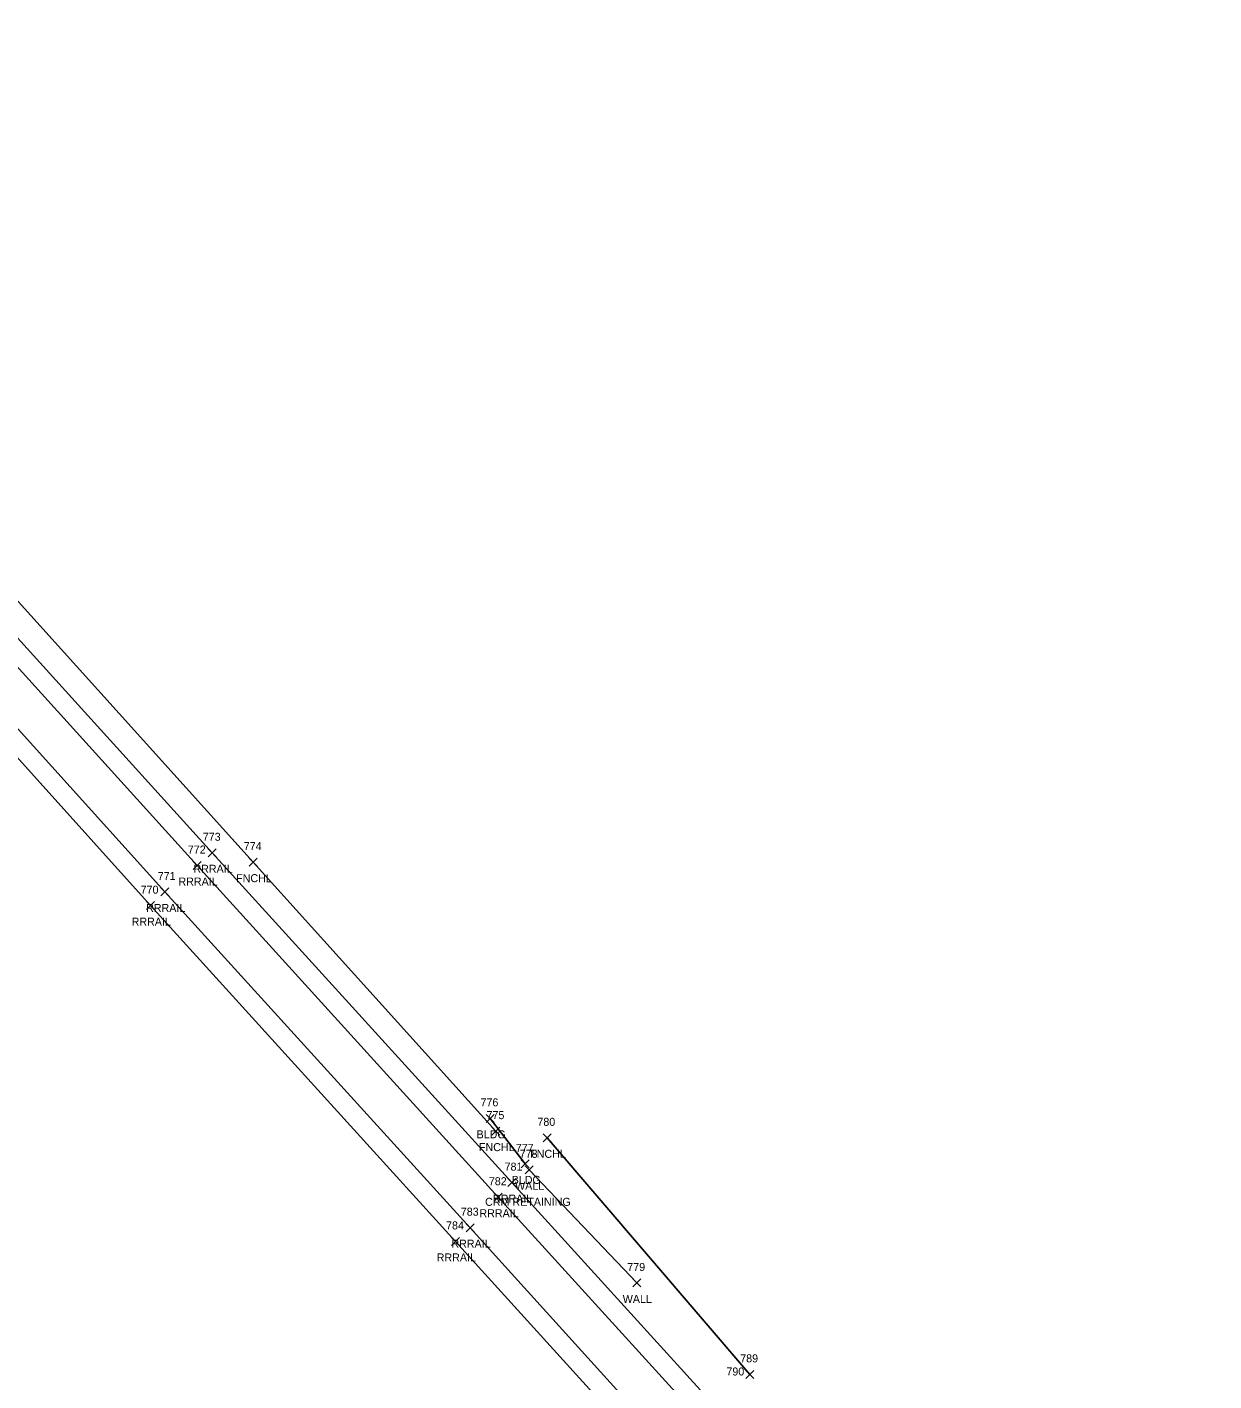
# Model space of a CAD drawing. Extents: x 1638029 to 1638889, y 618768 to 620505.
# Drawn here: x 1638352.1 to 1638648.8, y 619965.1 to 620303.6 of the extents above; entities that cross this region are included whole.
import ezdxf

# ---------------------------------------------------------------- set-up
doc = ezdxf.new("R2010")
doc.units = 0
for name, color, linetype in [('L_A', 7, 'Continuous'), ('L_C', 7, 'Continuous'), ('L_I', 7, 'Continuous'), ('L_TIC', 7, 'Continuous'), ('LBC', 7, 'Continuous'), ('LFNC', 7, 'Continuous'), ('LW', 7, 'Continuous'), ('R_A', 7, 'Continuous'), ('R_I', 7, 'Continuous'), ('R_TIC', 7, 'Continuous'), ('RR', 7, 'Continuous')]:
    doc.layers.add(name, color=color, linetype=linetype)

msp = doc.modelspace()

# ---------------------------------------------------------------- linework, layer by layer
at = {"layer": 'L_TIC'}
for points in [[(1638407.62, 620093.82), (1638409.62, 620095.82)], [(1638409.62, 620093.82), (1638407.62, 620095.82)], [(1638466.87, 620029.78), (1638468.87, 620031.78)], [(1638468.87, 620029.78), (1638466.87, 620031.78)], [(1638468.31, 620026.58), (1638470.31, 620028.58)], [(1638470.31, 620026.58), (1638468.31, 620028.58)], [(1638481.12, 620024.91), (1638483.12, 620026.91)], [(1638483.12, 620024.91), (1638481.12, 620026.91)], [(1638475.65, 620018.4), (1638477.65, 620020.4)], [(1638477.65, 620018.4), (1638475.65, 620020.4)], [(1638476.6, 620016.91), (1638478.6, 620018.91)], [(1638478.6, 620016.91), (1638476.6, 620018.91)], [(1638503.51, 619988.62), (1638505.51, 619990.62)], [(1638505.51, 619988.62), (1638503.51, 619990.62)], [(1638531.74, 619965.78), (1638533.74, 619967.78)], [(1638533.74, 619965.78), (1638531.74, 619967.78)]]:
    msp.add_lwpolyline(points, dxfattribs=at)
at = {"layer": 'LBC'}
msp.add_lwpolyline([(1638467.87, 620030.78), (1638476.65, 620019.4)], dxfattribs=at)
at = {"layer": 'LFNC'}
for points in [[(1638283.51, 620233.52), (1638308.83, 620205.48), (1638408.62, 620094.82), (1638469.31, 620027.58)], [(1638482.12, 620025.91), (1638532.74, 619966.78)]]:
    msp.add_lwpolyline(points, dxfattribs=at)
at = {"layer": 'LW'}
msp.add_lwpolyline([(1638477.6, 620017.91), (1638504.51, 619989.62)], dxfattribs=at)
at = {"layer": 'R_TIC'}
for points in [[(1638397.39, 620096.17), (1638399.39, 620098.17)], [(1638399.39, 620096.17), (1638397.39, 620098.17)], [(1638393.65, 620092.98), (1638395.65, 620094.98)], [(1638395.65, 620092.98), (1638393.65, 620094.98)], [(1638385.57, 620086.37), (1638387.57, 620088.37)], [(1638387.57, 620086.37), (1638385.57, 620088.37)], [(1638381.95, 620082.95), (1638383.95, 620084.95)], [(1638383.95, 620082.95), (1638381.95, 620084.95)], [(1638472.27, 620013.71), (1638474.27, 620015.71)], [(1638474.27, 620013.71), (1638472.27, 620015.71)], [(1638468.89, 620010.06), (1638470.89, 620012.06)], [(1638470.89, 620010.06), (1638468.89, 620012.06)], [(1638461.88, 620002.45), (1638463.88, 620004.45)], [(1638463.88, 620002.45), (1638461.88, 620004.45)], [(1638458.2, 619999.01), (1638460.2, 620001.01)], [(1638460.2, 619999.01), (1638458.2, 620001.01)]]:
    msp.add_lwpolyline(points, dxfattribs=at)
at = {"layer": 'RR'}
for points in [[(1638117.2, 620500.03), (1638126.53, 620471.54), (1638137.23, 620443.64), (1638146.58, 620422.4), (1638162.72, 620390.25), (1638178.78, 620362.34), (1638206.73, 620318.99), (1638221.73, 620298.51), (1638231.34, 620286.06), (1638247.72, 620265.63), (1638271.6, 620237.56), (1638302.87, 620202.63), (1638319.77, 620183.84), (1638340.9, 620160.55), (1638398.39, 620097.17), (1638473.27, 620014.71), (1638530.28, 619952.03), (1638576.7, 619900.87), (1638602.43, 619872.23), (1638628.75, 619841.68), (1638648.78, 619815.3)], [(1638112.47, 620498.54), (1638121.85, 620470.07), (1638132.7, 620441.63), (1638142.09, 620420.29), (1638158.38, 620387.98), (1638174.67, 620359.55), (1638202.82, 620316.02), (1638218.22, 620294.92), (1638227.34, 620283.09), (1638243.87, 620262.45), (1638266.59, 620235.71), (1638298.84, 620199.7), (1638316.08, 620180.56), (1638337.37, 620157.11), (1638394.65, 620093.98), (1638469.89, 620011.06), (1638526.76, 619948.51), (1638573.25, 619897.28), (1638598.73, 619868.77), (1638625.03, 619838.36), (1638644.96, 619812.19)], [(1638221.31, 620298.23), (1638230.93, 620285.59), (1638246.32, 620264.59), (1638266.59, 620235.71), (1638293.43, 620196.21), (1638308.67, 620175.28), (1638330, 620150.06), (1638386.57, 620087.37), (1638462.88, 620003.45), (1638518.49, 619941.93), (1638565.29, 619889.65), (1638590.21, 619860.51), (1638615.55, 619828.52), (1638634.05, 619803.38)], [(1638218.22, 620294.92), (1638227.01, 620282.65), (1638242.37, 620261.41), (1638263.25, 620232.01), (1638289.27, 620193.61), (1638304.74, 620172.29), (1638326.19, 620147.02), (1638382.95, 620083.95), (1638459.2, 620000.01), (1638514.66, 619938.83), (1638562.01, 619885.9), (1638586.02, 619857.93), (1638612.02, 619825.03), (1638629.76, 619800.91)]]:
    msp.add_lwpolyline(points, dxfattribs=at)

# ---------------------------------------------------------------- texts
at = {"layer": 'L_A'}
for s, p in [('FNCHL', (1638404.37, 620089.82)), ('BLDG', (1638464.46, 620025.78)), ('FNCHL', (1638465.06, 620022.58)), ('FNCHL', (1638477.87, 620020.91)), ('BLDG', (1638473.24, 620014.4)), ('WALL', (1638474.09, 620012.91)), ('WALL', (1638501, 619984.62))]:
    msp.add_text(s, height=2, dxfattribs=at).set_placement(p)
at = {"layer": 'L_C'}
msp.add_text('CRM RETAINING', height=2, dxfattribs=at).set_placement((1638466.6, 620008.91))
at = {"layer": 'L_I'}
for s, p in [('774', (1638406.26, 620097.82)), ('776', (1638465.45, 620033.78)), ('775', (1638466.95, 620030.58)), ('780', (1638479.67, 620028.91)), ('777', (1638474.28, 620022.4)), ('778', (1638475.24, 620020.91)), ('779', (1638502.14, 619992.62)), ('789', (1638530.37, 619969.78)), ('790', (1638526.92, 619966.5))]:
    msp.add_text(s, height=2, dxfattribs=at).set_placement(p)
at = {"layer": 'R_A'}
for p in [(1638393.68, 620092.17), (1638389.94, 620088.98), (1638381.86, 620082.37), (1638378.24, 620078.95), (1638468.56, 620009.71), (1638465.18, 620006.06), (1638458.17, 619998.45), (1638454.5, 619995.01)]:
    msp.add_text('RRRAIL', height=2, dxfattribs=at).set_placement(p)
at = {"layer": 'R_I'}
for s, p in [('773', (1638396.03, 620100.17)), ('772', (1638392.29, 620096.98)), ('771', (1638384.77, 620090.37)), ('770', (1638380.5, 620086.95)), ('781', (1638471.47, 620017.71)), ('782', (1638467.53, 620014.06)), ('783', (1638460.52, 620006.45)), ('784', (1638456.84, 620003.01))]:
    msp.add_text(s, height=2, dxfattribs=at).set_placement(p)

doc.saveas('drawing.dxf')
